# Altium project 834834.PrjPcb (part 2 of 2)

## Sheet 834834_ESCON2_EB_Nano_Nano-CAN-RS422.SchDoc
size A3; SheetNumber: 4; SheetTotal: 4; Created: MMAGHIN; Modified: MMAGADHA; Reviewed: MMAGMHA; CreatedDate: 10.07.2023; ReviewedDate: 03.10.2023; ModifiedDate1: 28.09.2023
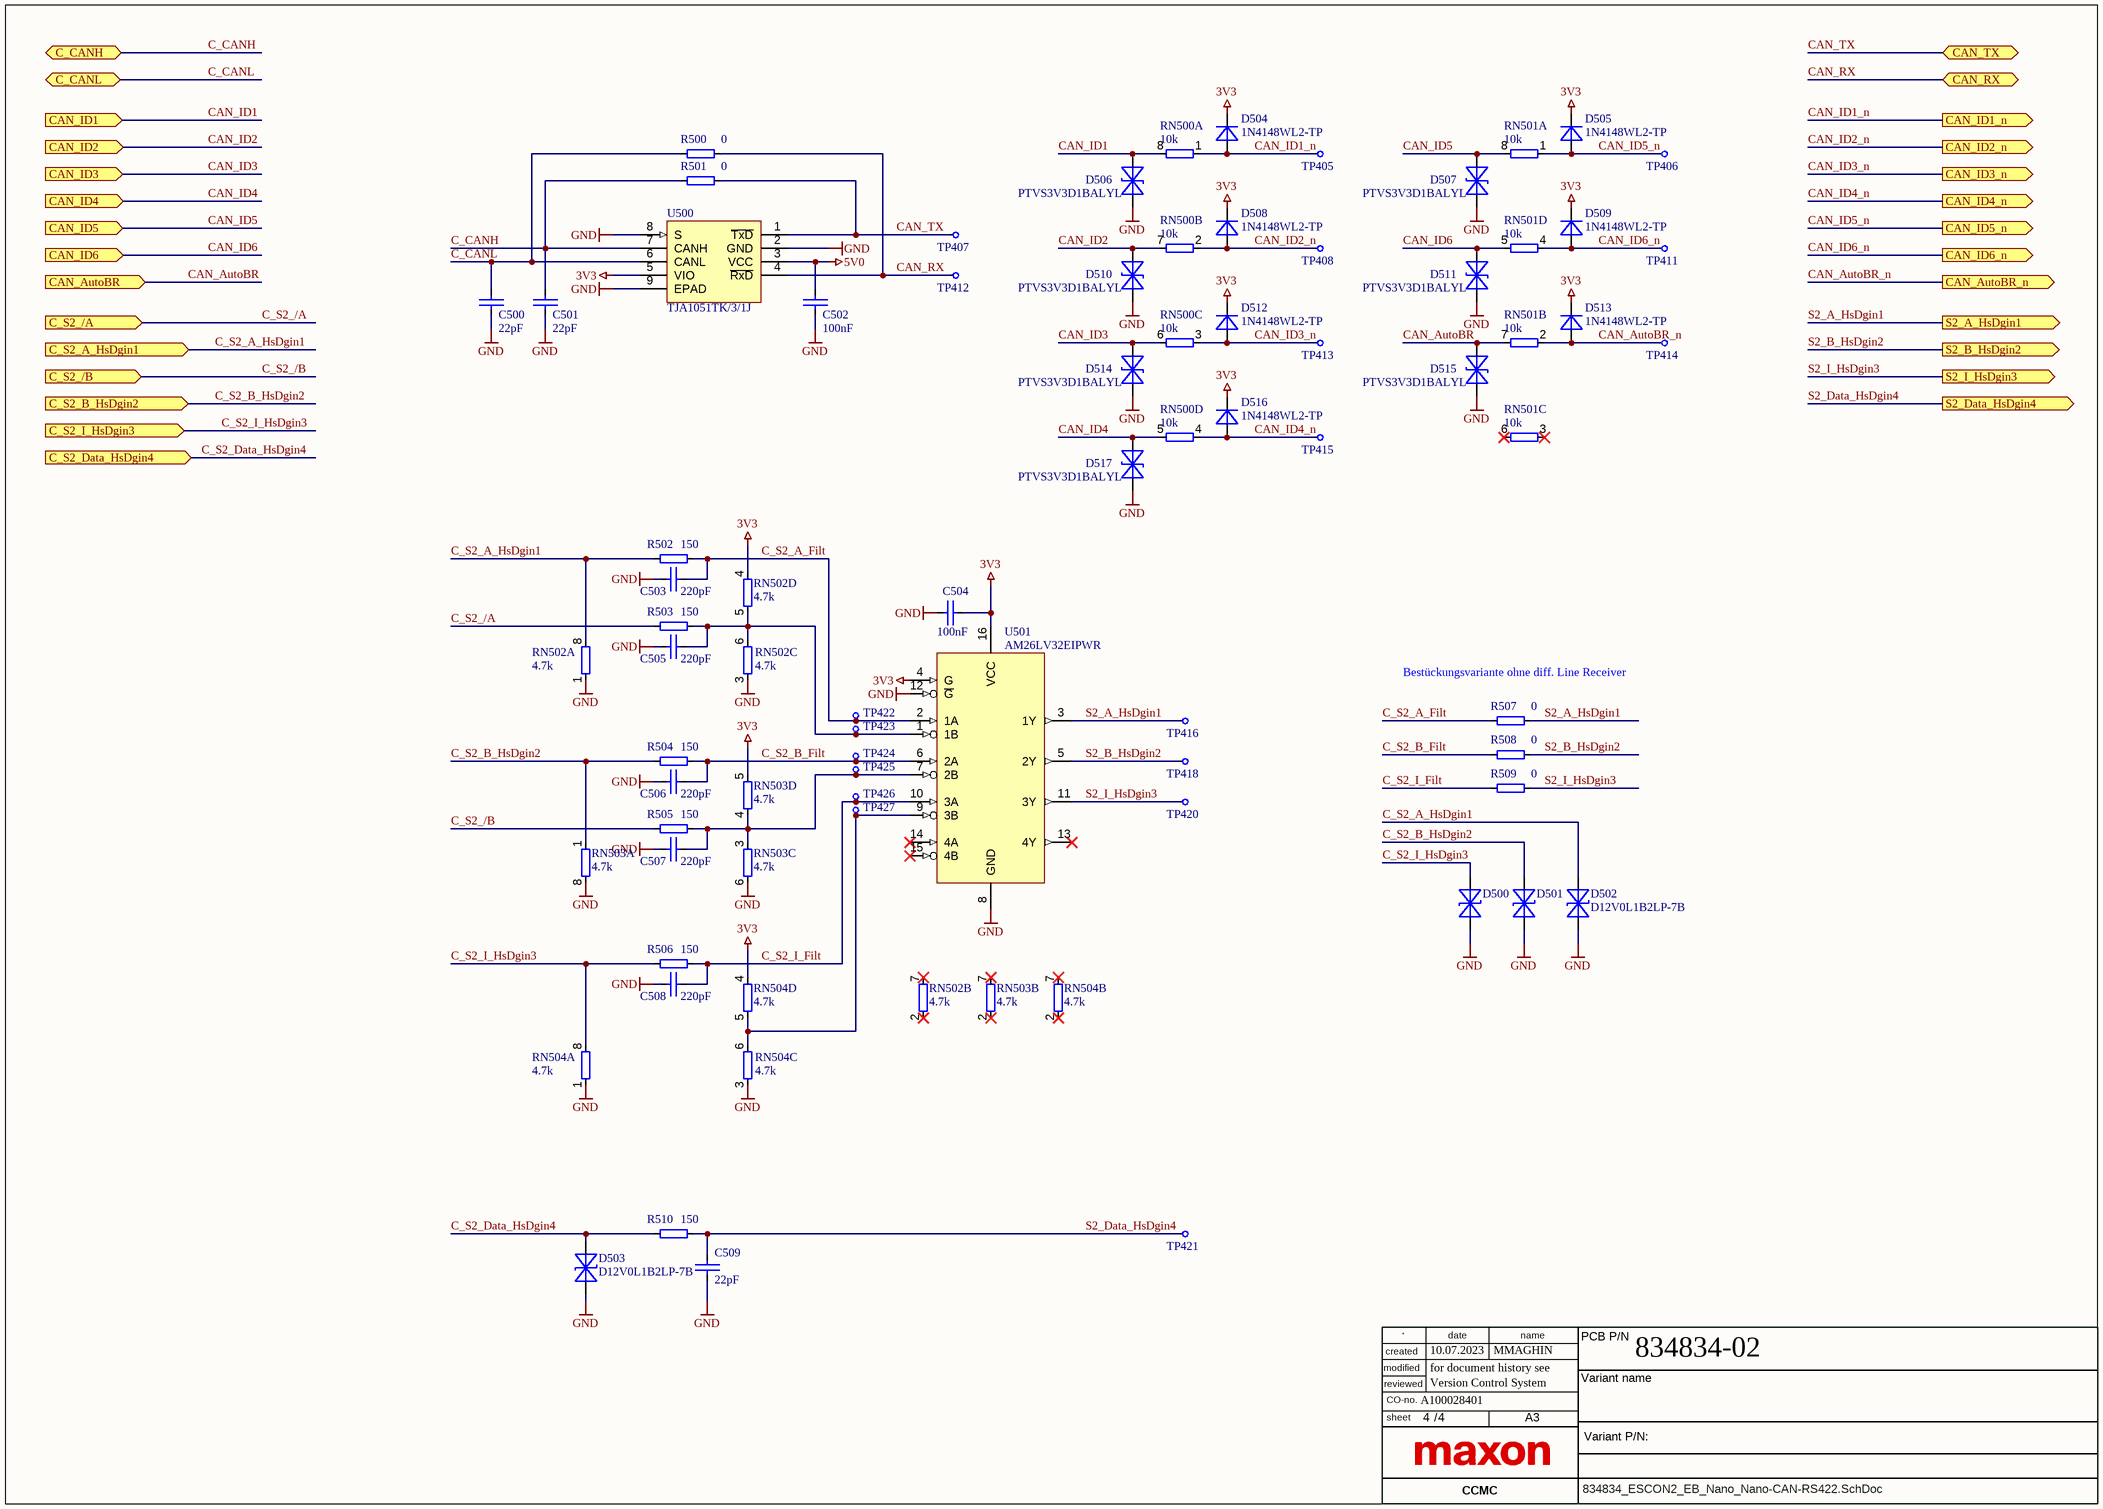
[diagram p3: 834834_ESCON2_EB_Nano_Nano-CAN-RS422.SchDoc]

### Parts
C500  value 22pF  [CAPC100X50X70L25N]  (hidden comment: 0402 22pF)
C501  value 22pF  [CAPC100X50X70L25N]  (hidden comment: 0402 22pF)
C502  value 100nF  [CAPC100X50X70L25N]  (hidden comment: 0402 100nF)
C503  value 220pF  [CAPC100X50X70L25N]  (hidden comment: 0402 220pF)
C504  value 100nF  [CAPC100X50X70L25N]  (hidden comment: 0402 100nF)
C505  value 220pF  [CAPC100X50X70L25N]  (hidden comment: 0402 220pF)
C506  value 220pF  [CAPC100X50X70L25N]  (hidden comment: 0402 220pF)
C507  value 220pF  [CAPC100X50X70L25N]  (hidden comment: 0402 220pF)
C508  value 220pF  [CAPC100X50X70L25N]  (hidden comment: 0402 220pF)
C509  value 22pF  [CAPC100X50X70L25N]  (hidden comment: 0402 22pF)
D500  D12V0L1B2LP-7B  [DIONPDFN2_102X60X60L25X50N]  (value not drawn)
D501  D12V0L1B2LP-7B  [DIONPDFN2_102X60X60L25X50N]  (value not drawn)
D502  D12V0L1B2LP-7B  [DIONPDFN2_102X60X60L25X50N]
D503  D12V0L1B2LP-7B  [DIONPDFN2_102X60X60L25X50N]
D504  1N4148WL2-TP  [DIODFN2_102X60X60L25X50N]
D505  1N4148WL2-TP  [DIODFN2_102X60X60L25X50N]
D506  PTVS3V3D1BALYL  [DIONPDFN2_102X60X60L25X50N]
D507  PTVS3V3D1BALYL  [DIONPDFN2_102X60X60L25X50N]
D508  1N4148WL2-TP  [DIODFN2_102X60X60L25X50N]
D509  1N4148WL2-TP  [DIODFN2_102X60X60L25X50N]
D510  PTVS3V3D1BALYL  [DIONPDFN2_102X60X60L25X50N]
D511  PTVS3V3D1BALYL  [DIONPDFN2_102X60X60L25X50N]
D512  1N4148WL2-TP  [DIODFN2_102X60X60L25X50N]
D513  1N4148WL2-TP  [DIODFN2_102X60X60L25X50N]
D514  PTVS3V3D1BALYL  [DIONPDFN2_102X60X60L25X50N]
D515  PTVS3V3D1BALYL  [DIONPDFN2_102X60X60L25X50N]
D516  1N4148WL2-TP  [DIODFN2_102X60X60L25X50N]
D517  PTVS3V3D1BALYL  [DIONPDFN2_102X60X60L25X50N]
R500  value 0  [RESC100X52X40L22N]  (hidden comment: 0402 0)
R501  value 0  [RESC100X52X40L22N]  (hidden comment: 0402 0)
R502  value 150  [RESC100X52X40L22N]  (hidden comment: 0402 150R)
R503  value 150  [RESC100X52X40L22N]  (hidden comment: 0402 150R)
R504  value 150  [RESC100X52X40L22N]  (hidden comment: 0402 150R)
R505  value 150  [RESC100X52X40L22N]  (hidden comment: 0402 150R)
R506  value 150  [RESC100X52X40L22N]  (hidden comment: 0402 150R)
R507  value 0  [RESC100X52X40L22N]  (hidden comment: 0402 0)
R508  value 0  [RESC100X52X40L22N]  (hidden comment: 0402 0)
R509  value 0  [RESC100X52X40L22N]  (hidden comment: 0402 0)
R510  value 150  [RESC100X52X40L22N]  (hidden comment: 0402 150R)
RN500  value 10k  [RESCAXS8P50_200X102X55L30X30N]  (hidden comment: 4x0402 10k)  (parts A,B,C,D of 4)
RN501  value 10k  [RESCAXS8P50_200X102X55L30X30N]  (hidden comment: 4x0402 10k)  (parts A,B,C,D of 4)
RN502  value 4.7k  [RESCAXS8P50_200X102X55L30X30N]  (hidden comment: 4x0402 4.7k)  (parts A,B,C,D of 4)
RN503  value 4.7k  [RESCAXS8P50_200X102X55L30X30N]  (hidden comment: 4x0402 4.7k)  (parts A,B,C,D of 4)
RN504  value 4.7k  [RESCAXS8P50_200X102X55L30X30N]  (hidden comment: 4x0402 4.7k)  (parts A,B,C,D of 4)
TP405  TPc120  [TESTPOINT_c120]  (value not drawn)  (no BOM)
TP406  TPc120  [TESTPOINT_c120]  (value not drawn)  (no BOM)
TP407  TPc120  [TESTPOINT_c120]  (value not drawn)  (no BOM)
TP408  TPc120  [TESTPOINT_c120]  (value not drawn)  (no BOM)
TP411  TPc120  [TESTPOINT_c120]  (value not drawn)  (no BOM)
TP412  TPc120  [TESTPOINT_c120]  (value not drawn)  (no BOM)
TP413  TPc120  [TESTPOINT_c120]  (value not drawn)  (no BOM)
TP414  TPc120  [TESTPOINT_c120]  (value not drawn)  (no BOM)
TP415  TPc120  [TESTPOINT_c120]  (value not drawn)  (no BOM)
TP416  TPc120  [TESTPOINT_c120]  (value not drawn)  (no BOM)
TP418  TPc120  [TESTPOINT_c120]  (value not drawn)  (no BOM)
TP420  TPc120  [TESTPOINT_c120]  (value not drawn)  (no BOM)
TP421  TPc120  [TESTPOINT_c120]  (value not drawn)  (no BOM)
TP422  TPc120  [TESTPOINT_c120]  (value not drawn)  (no BOM)
TP423  TPc120  [TESTPOINT_c120]  (value not drawn)  (no BOM)
TP424  TPc120  [TESTPOINT_c120]  (value not drawn)  (no BOM)
TP425  TPc120  [TESTPOINT_c120]  (value not drawn)  (no BOM)
TP426  TPc120  [TESTPOINT_c120]  (value not drawn)  (no BOM)
TP427  TPc120  [TESTPOINT_c120]  (value not drawn)  (no BOM)
U500  TJA1051TK/3/1J  [SON9P65_300X300X100L40X30T240X160N]
U501  AM26LV32EIPWR  [SOP16P65_500X640X120L83X24N]

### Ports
C_CANH (bidir), C_CANL (bidir), C_S2_/A (in), C_S2_/B (in), C_S2_A_HsDgin1 (in), C_S2_B_HsDgin2 (in), C_S2_Data_HsDgin4 (in), C_S2_I_HsDgin3 (in), CAN_AutoBR (in), CAN_AutoBR_n (out), CAN_ID1 (in), CAN_ID1_n (out), CAN_ID2 (in), CAN_ID2_n (out), CAN_ID3 (in), CAN_ID3_n (out), CAN_ID4 (in), CAN_ID4_n (out), CAN_ID5 (in), CAN_ID5_n (out), CAN_ID6 (in), CAN_ID6_n (out), CAN_RX (bidir), CAN_TX (bidir), S2_A_HsDgin1 (out), S2_B_HsDgin2 (out), S2_Data_HsDgin4 (out), S2_I_HsDgin3 (out)

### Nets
3V3: C504.1 D504.1(C) D505.1(C) D508.1(C) D509.1(C) D512.1(C) D513.1(C) D516.1(C) RN502.4 RN503.5 RN504.4 U500.5(VIO) U501.4(G) U501.16(VCC)
5V0: C502.2 U500.3(VCC)
GND: C500.2 C501.2 C502.1 C503.2 C504.2 C505.2 C506.2 C507.2 C508.2 C509.2 D500.1 D501.1 D502.1 D503.1 D506.2 D507.2 D510.2 D511.2 D514.2 D515.2 D517.2 RN502.1 RN502.3 RN503.6 RN503.8 RN504.1 RN504.3 U500.2(GND) U500.8(S) U500.9(EPAD) U501.8(GND) U501.12(~{G})
C_CANH: C501.1 R501.2 U500.7(CANH) ; port C_CANH
C_CANL: C500.1 R500.2 U500.6(CANL) ; port C_CANL
C_S2_/A: R503.1 ; port C_S2_/A
C_S2_/B: R505.1 ; port C_S2_/B
C_S2_A_Filt: C503.1 R502.2 R507.2 TP422.1 U501.2(1A)
C_S2_A_HsDgin1: D502.2 R502.1 RN502.8 ; port C_S2_A_HsDgin1
C_S2_B_Filt: C506.1 R504.2 R508.2 TP424.1 U501.6(2A)
C_S2_B_HsDgin2: D501.2 R504.1 RN503.1 ; port C_S2_B_HsDgin2
C_S2_Data_HsDgin4: D503.2 R510.1 ; port C_S2_Data_HsDgin4
C_S2_I_Filt: C508.1 R506.2 R509.2 TP426.1 U501.10(3A)
C_S2_I_HsDgin3: D500.2 R506.1 RN504.8 ; port C_S2_I_HsDgin3
CAN_AutoBR: D515.1 RN501.7 ; port CAN_AutoBR
CAN_AutoBR_n: D513.2(A) RN501.2 TP414.1 ; port CAN_AutoBR_n
CAN_ID1: D506.1 RN500.8 ; port CAN_ID1
CAN_ID1_n: D504.2(A) RN500.1 TP405.1 ; port CAN_ID1_n
CAN_ID2: D510.1 RN500.7 ; port CAN_ID2
CAN_ID2_n: D508.2(A) RN500.2 TP408.1 ; port CAN_ID2_n
CAN_ID3: D514.1 RN500.6 ; port CAN_ID3
CAN_ID3_n: D512.2(A) RN500.3 TP413.1 ; port CAN_ID3_n
CAN_ID4: D517.1 RN500.5 ; port CAN_ID4
CAN_ID4_n: D516.2(A) RN500.4 TP415.1 ; port CAN_ID4_n
CAN_ID5: D507.1 RN501.8 ; port CAN_ID5
CAN_ID5_n: D505.2(A) RN501.1 TP406.1 ; port CAN_ID5_n
CAN_ID6: D511.1 RN501.5 ; port CAN_ID6
CAN_ID6_n: D509.2(A) RN501.4 TP411.1 ; port CAN_ID6_n
CAN_RX: R500.1 TP412.1 U500.4(~{RxD}) ; port CAN_RX
CAN_TX: R501.1 TP407.1 U500.1(~{TxD}) ; port CAN_TX
S2_A_HsDgin1: R507.1 TP416.1 U501.3(1Y) ; port S2_A_HsDgin1
S2_B_HsDgin2: R508.1 TP418.1 U501.5(2Y) ; port S2_B_HsDgin2
S2_Data_HsDgin4: C509.1 R510.2 TP421.1 ; port S2_Data_HsDgin4
S2_I_HsDgin3: R509.1 TP420.1 U501.11(3Y) ; port S2_I_HsDgin3
NetC505_1: C505.1 R503.2 RN502.5 RN502.6 TP423.1 U501.1(1B)
NetC507_1: C507.1 R505.2 RN503.3 RN503.4 TP425.1 U501.7(2B)
NetRN504_5: RN504.5 RN504.6 TP427.1 U501.9(3B)

Not connected (* = marked no-connect by the designer): RN501 3* 6*; RN502 2* 7*; RN503 2* 7*; RN504 2* 7*; U501 13(4Y)* 14(4A)* 15(4B)*

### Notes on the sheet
- (near R507) Bestückungsvariante ohne diff. Line Receiver

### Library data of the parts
C500 C501 C509 = CMP-000706-3: 22pF C0G/NP0 >=50V 10%; Part Number: Ceramic, 0402, 22pF, 10%, >=50V, C0G/NP0, @, Soft Termination: N, -55°C to 125°C; Manufacturer: X; Case (Metric): 1005; Soft Termination: N; Maximum Working Voltage: 50V
C502 C504 = CMP-000709-3: 100nF X7R >=16V 20%; Part Number: Ceramic, 0402, 100nF, 20%, >=16V, X7R, @, Soft Termination: N, -55°C to 125°C; Manufacturer: X; Maximum Working Voltage: 16V; Soft Termination: N; Case (Metric): 1005
C503 C505-C508 = CMP-000726-3: 220pF C0G/NP0/X7R >=50V 10%; Manufacturer: X; Part Number: Ceramic, 0402, 220pF, 10%, >=50V, C0G/NP0/X7R, @, Soft Termination: N, -55°C to 125°C; Maximum Working Voltage: 50V; Case (Metric): 1005; Soft Termination: N
D500-D503 = CMP-001106-5: Transient Voltage Suppressor Diode, 12V V(RWM), Bidirectional, 100W, 1 Element, SOD-882/DFN1006; Manufacturer: Diodes; Element Configuration: Single; Breakdown Voltage: 13V; Polarity: Bipolar
D504 D505 D508 D509 D512 D513 D516 = CMP-000606-13: Diode Switching, >=70V, >=150mA, SOD882/DFN1006/0402/SOD-923F; Manufacturer: MCC; Polarity: Unipolar; Recovery time: 4ns; Reverse Voltage: 70V; Element Configuration: Single; RMS Current: 150mA
D506 D507 D510 D511 D514 D515 D517 = CMP-001117-7: Transient Voltage Suppressor Diode, 3.3V V(RWM), Bidirectional, 30W, 1 Element, SOD-882/DFN1006; Manufacturer: Nexperia; Element Configuration: Single; Breakdown Voltage: 4V; Polarity: Bipolar
R500 R501 R507-R509 = CMP-000466-10: 0R Jumper; Part Number: Thick-Film, 0402, 0, -55°C to 155°C; Manufacturer: X; Case (Metric): 1050; RMS Current: 1A; Maximum Overload Voltage: 100V; Max Junction Temperature: 155°C; Maximum Working Voltage: 50V
R502-R506 R510 = CMP-000169-11: 150R 1% 62.5mW 100ppm; Part Number: Thick-Film, 0402, 150, 1%, 62.5mW@70°C, 50V, 100ppm, -55°C to 155°C; Manufacturer: X; Max Junction Temperature: 155°C; AECQ: N; Case (Metric): 1050; Power Rating Temperature: 70°C; Maximum Working Voltage: 50V; Maximum Overload Voltage: 100V
RN500 RN501 = CMP-000792-5: 4x10k 5% 62.5mW 200ppm; Part Number: Thick-Film Concave/Convex, 4x0402, 10k, 5%, 62.5mW@70°C, 25V, 200ppm, -55°C to 125°C; Manufacturer: X; Max Junction Temperature: 125°C; AECQ: N; Case (Metric): 2010; Power Rating Temperature: 70°C; Maximum Working Voltage: 25V; Maximum Overload Voltage: 50V
RN502-RN504 = CMP-000784-5: 4x4.7k 5% 62.5mW 200ppm; Part Number: Thick-Film Concave/Convex, 4x0402, 4.7k, 5%, 62.5mW@70°C, 25V, 200ppm, -55°C to 125°C; Manufacturer: X; Max Junction Temperature: 125°C; AECQ: N; Case (Metric): 2010; Power Rating Temperature: 70°C; Maximum Working Voltage: 25V; Maximum Overload Voltage: 50V
TP405-TP408 TP411-TP416 TP418 TP420-TP427 = CMP-000014-7: Test Point; 1 pin, 1.20 mm D
U500 = CMP-000672-8: High Speed CAN Transceiver, Single, 5V, HVSON-8; Manufacturer: NXP Semiconductors; Min Supply Voltage: 4.5V; Max Supply Voltage: 5.5V
U501 = CMP-001174-5: Low-Voltage High-Speed Quadruple Differential Line Receiver With +/-15-kV IEC ESD 16-TSSOP -40 to 85°C; Manufacturer: Texas Instruments; Max Supply Voltage: 3.6V; Min Supply Voltage: 3V

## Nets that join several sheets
3V3: 834834_ESCON2_EB_Nano_Common-Components (C200.2 TP202.1 U200.5 X200.1), 834834_ESCON2_EB_Nano_Nano-Components (6 pins), 834834_ESCON2_EB_Nano_Nano-CAN-RS422 (14 pins)
5V0: 834834_ESCON2_EB_Nano_Common-Components (8 pins), 834834_ESCON2_EB_Nano_Nano-Components (10 pins), 834834_ESCON2_EB_Nano_Nano-CAN-RS422 (C502.2 U500.3)
5V0_sensor1_2: 834834_ESCON2_EB_Nano_Common-Components (D201.2 X4.5 X5.2), 834834_ESCON2_EB_Nano_Nano-Components (R421.1 R429.2 TP404.1)
C_VP: 834834_ESCON2_EB_Nano_Common-Components (TP201.1 X1.2), 834834_ESCON2_EB_Nano_Nano-Components (F400.1)
GND: 834834_ESCON2_EB_Nano_Common-Components (65 pins), 834834_ESCON2_EB_Nano_Nano-Components (57 pins), 834834_ESCON2_EB_Nano_Nano-CAN-RS422 (32 pins)
C_AnIN1+: 834834_ESCON2_EB_Nano_Common-Components (TP230.1 X8.1), 834834_ESCON2_EB_Nano_Nano-Components (D404.1 X400a.26 X400b.26)
C_AnIN2+: 834834_ESCON2_EB_Nano_Common-Components (TP232.1 X8.3), 834834_ESCON2_EB_Nano_Nano-Components (D403.1 X400a.28 X400b.28)
C_AnOUT1: 834834_ESCON2_EB_Nano_Common-Components (TP234.1 X8.5), 834834_ESCON2_EB_Nano_Nano-Components (D406.2 X400a.30 X400b.30)
C_AnOUT2: 834834_ESCON2_EB_Nano_Common-Components (TP237.1 X8.6), 834834_ESCON2_EB_Nano_Nano-Components (D405.2 X400a.32 X400b.32)
C_CANH: 834834_ESCON2_EB_Nano_Common-Components (SW1.7 TP240.1 X11.1 X12.1), 834834_ESCON2_EB_Nano_Nano-CAN-RS422 (C501.1 R501.2 U500.7)
C_CANL: 834834_ESCON2_EB_Nano_Common-Components (R209.2 TP241.1 X11.2 X12.2), 834834_ESCON2_EB_Nano_Nano-CAN-RS422 (C500.1 R500.2 U500.6)
C_DigIN1: 834834_ESCON2_EB_Nano_Common-Components (D203.2 TP204.1 X7.1), 834834_ESCON2_EB_Nano_Nano-Components (RN400.5 RN400.6)
C_DigIN2: 834834_ESCON2_EB_Nano_Common-Components (D202.2 TP205.1 X7.2), 834834_ESCON2_EB_Nano_Nano-Components (RN400.7 RN400.8)
C_DigIN3: 834834_ESCON2_EB_Nano_Common-Components (D210.2 TP269.1 X7.3), 834834_ESCON2_EB_Nano_Nano-Components (X400a.27 X400b.27)
C_DigIN4: 834834_ESCON2_EB_Nano_Common-Components (D209.2 TP270.1 X7.4), 834834_ESCON2_EB_Nano_Nano-Components (X400a.29 X400b.29)
C_MotorTemp: 834834_ESCON2_EB_Nano_Common-Components (TP260.1 X16.2), 834834_ESCON2_EB_Nano_Nano-Components (C421.2 Q400.2 R427.2)
C_S1_Hall1: 834834_ESCON2_EB_Nano_Common-Components (TP266.1 X4.1), 834834_ESCON2_EB_Nano_Nano-Components (X400a.13 X400b.13)
C_S1_Hall2: 834834_ESCON2_EB_Nano_Common-Components (TP267.1 X4.2), 834834_ESCON2_EB_Nano_Nano-Components (X400a.15 X400b.15)
C_S1_Hall3: 834834_ESCON2_EB_Nano_Common-Components (TP268.1 X4.3), 834834_ESCON2_EB_Nano_Nano-Components (X400a.17 X400b.17)
C_S2_/A: 834834_ESCON2_EB_Nano_Common-Components (TP216.1 X5.5), 834834_ESCON2_EB_Nano_Nano-CAN-RS422 (R503.1)
C_S2_/B: 834834_ESCON2_EB_Nano_Common-Components (TP218.1 X5.7), 834834_ESCON2_EB_Nano_Nano-CAN-RS422 (R505.1)
C_S2_A_HsDgin1: 834834_ESCON2_EB_Nano_Common-Components (TP217.1 X5.6), 834834_ESCON2_EB_Nano_Nano-CAN-RS422 (D502.2 R502.1 RN502.8)
C_S2_B_HsDgin2: 834834_ESCON2_EB_Nano_Common-Components (TP219.1 X5.8), 834834_ESCON2_EB_Nano_Nano-CAN-RS422 (D501.2 R504.1 RN503.1)
C_S2_Data_HsDgin4: 834834_ESCON2_EB_Nano_Common-Components (TP213.1 X5.1), 834834_ESCON2_EB_Nano_Nano-CAN-RS422 (D503.2 R510.1)
C_S2_I_HsDgin3: 834834_ESCON2_EB_Nano_Common-Components (TP220.1 X5.10), 834834_ESCON2_EB_Nano_Nano-CAN-RS422 (D500.2 R506.1 RN504.8)
C_USB_D+: 834834_ESCON2_EB_Nano_Common-Components (D208.5 TP251.1 X13.AB6), 834834_ESCON2_EB_Nano_Nano-Components (X400a.46 X400b.46)
C_USB_D-: 834834_ESCON2_EB_Nano_Common-Components (D208.1 TP252.1 X13.AB7), 834834_ESCON2_EB_Nano_Nano-Components (X400a.48 X400b.48)
C_USB_VBUS: 834834_ESCON2_EB_Nano_Common-Components (C206.2 TP247.1 X13.AB49), 834834_ESCON2_EB_Nano_Nano-Components (X400a.44 X400b.44)
C_W1: 834834_ESCON2_EB_Nano_Common-Components (TP207.1 X3.1), 834834_ESCON2_EB_Nano_Nano-Components (C402.2 C405.2 L400.2)
C_W2: 834834_ESCON2_EB_Nano_Common-Components (TP208.1 X3.2), 834834_ESCON2_EB_Nano_Nano-Components (C403.2 C406.2 L401.2)
C_W3: 834834_ESCON2_EB_Nano_Common-Components (TP209.1 X3.3), 834834_ESCON2_EB_Nano_Nano-Components (C404.2 C407.2 L402.2)
CAN_AutoBR: 834834_ESCON2_EB_Nano_Common-Components (SW1.11 TP253.1), 834834_ESCON2_EB_Nano_Nano-CAN-RS422 (D515.1 RN501.7)
CAN_AutoBR_n: 834834_ESCON2_EB_Nano_Nano-Components (X400a.35 X400b.35), 834834_ESCON2_EB_Nano_Nano-CAN-RS422 (D513.2 RN501.2 TP414.1)
CAN_ID1: 834834_ESCON2_EB_Nano_Common-Components (SW1.16 TP239.1), 834834_ESCON2_EB_Nano_Nano-CAN-RS422 (D506.1 RN500.8)
CAN_ID1_n: 834834_ESCON2_EB_Nano_Nano-Components (X400a.37 X400b.37), 834834_ESCON2_EB_Nano_Nano-CAN-RS422 (D504.2 RN500.1 TP405.1)
CAN_ID2: 834834_ESCON2_EB_Nano_Common-Components (SW1.15 TP243.1), 834834_ESCON2_EB_Nano_Nano-CAN-RS422 (D510.1 RN500.7)
CAN_ID2_n: 834834_ESCON2_EB_Nano_Nano-Components (X400a.39 X400b.39), 834834_ESCON2_EB_Nano_Nano-CAN-RS422 (D508.2 RN500.2 TP408.1)
CAN_ID3: 834834_ESCON2_EB_Nano_Common-Components (SW1.14 TP245.1), 834834_ESCON2_EB_Nano_Nano-CAN-RS422 (D514.1 RN500.6)
CAN_ID3_n: 834834_ESCON2_EB_Nano_Nano-Components (X400a.41 X400b.41), 834834_ESCON2_EB_Nano_Nano-CAN-RS422 (D512.2 RN500.3 TP413.1)
CAN_ID4: 834834_ESCON2_EB_Nano_Common-Components (SW1.13 TP248.1), 834834_ESCON2_EB_Nano_Nano-CAN-RS422 (D517.1 RN500.5)
CAN_ID4_n: 834834_ESCON2_EB_Nano_Nano-Components (X400a.43 X400b.43), 834834_ESCON2_EB_Nano_Nano-CAN-RS422 (D516.2 RN500.4 TP415.1)
CAN_ID5: 834834_ESCON2_EB_Nano_Common-Components (SW1.12 TP250.1), 834834_ESCON2_EB_Nano_Nano-CAN-RS422 (D507.1 RN501.8)
CAN_ID5_n: 834834_ESCON2_EB_Nano_Nano-Components (X400a.45 X400b.45), 834834_ESCON2_EB_Nano_Nano-CAN-RS422 (D505.2 RN501.1 TP406.1)
CAN_ID6: 834834_ESCON2_EB_Nano_Common-Components (SW1.9 TP257.1), 834834_ESCON2_EB_Nano_Nano-CAN-RS422 (D511.1 RN501.5)
CAN_ID6_n: 834834_ESCON2_EB_Nano_Nano-Components (X400a.47 X400b.47), 834834_ESCON2_EB_Nano_Nano-CAN-RS422 (D509.2 RN501.4 TP411.1)
CAN_RX: 834834_ESCON2_EB_Nano_Nano-Components (X400a.53 X400b.53), 834834_ESCON2_EB_Nano_Nano-CAN-RS422 (R500.1 TP412.1 U500.4)
CAN_TX: 834834_ESCON2_EB_Nano_Nano-Components (X400a.51 X400b.51), 834834_ESCON2_EB_Nano_Nano-CAN-RS422 (R501.1 TP407.1 U500.1)
DBG_SWCLK: 834834_ESCON2_EB_Nano_Common-Components (TP222.1 X200.4), 834834_ESCON2_EB_Nano_Nano-Components (X400a.34 X400b.34)
DBG_SWDIO: 834834_ESCON2_EB_Nano_Common-Components (TP221.1 X200.2), 834834_ESCON2_EB_Nano_Nano-Components (X400a.36 X400b.36)
DigOUT1: 834834_ESCON2_EB_Nano_Common-Components (R214.2 TP235.1 U201.1 U201.2), 834834_ESCON2_EB_Nano_Nano-Components (X400a.31 X400b.31)
DigOUT2: 834834_ESCON2_EB_Nano_Common-Components (R215.2 TP236.1 U202.1 U202.2), 834834_ESCON2_EB_Nano_Nano-Components (X400a.33 X400b.33)
LED_Axis_gn: 834834_ESCON2_EB_Nano_Common-Components (R212.1 TP261.1), 834834_ESCON2_EB_Nano_Nano-Components (X400a.21 X400b.21)
LED_Axis_rd: 834834_ESCON2_EB_Nano_Common-Components (R211.1 TP258.1), 834834_ESCON2_EB_Nano_Nano-Components (X400a.19 X400b.19)
S2_A_HsDgin1: 834834_ESCON2_EB_Nano_Nano-Components (X400a.14 X400b.14), 834834_ESCON2_EB_Nano_Nano-CAN-RS422 (R507.1 TP416.1 U501.3)
S2_B_HsDgin2: 834834_ESCON2_EB_Nano_Nano-Components (X400a.16 X400b.16), 834834_ESCON2_EB_Nano_Nano-CAN-RS422 (R508.1 TP418.1 U501.5)
S2_Clock: 834834_ESCON2_EB_Nano_Common-Components (R213.2 TP206.1 U200.2), 834834_ESCON2_EB_Nano_Nano-Components (X400a.22 X400b.22)
S2_Data_HsDgin4: 834834_ESCON2_EB_Nano_Nano-Components (X400a.20 X400b.20), 834834_ESCON2_EB_Nano_Nano-CAN-RS422 (C509.1 R510.2 TP421.1)
S2_I_HsDgin3: 834834_ESCON2_EB_Nano_Nano-Components (X400a.18 X400b.18), 834834_ESCON2_EB_Nano_Nano-CAN-RS422 (R509.1 TP420.1 U501.11)
SYS_/Reset: 834834_ESCON2_EB_Nano_Common-Components (C203.2 TP228.1 X200.10), 834834_ESCON2_EB_Nano_Nano-Components (X400a.38 X400b.38)
UART_RxD: 834834_ESCON2_EB_Nano_Common-Components (C212.2 TP212.1 U203.12), 834834_ESCON2_EB_Nano_Nano-Components (X400a.54 X400b.54)
UART_TxD: 834834_ESCON2_EB_Nano_Common-Components (TP211.1 U203.11), 834834_ESCON2_EB_Nano_Nano-Components (R418.1)

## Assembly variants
834835: not fitted C212 C401 C408 C409 C410 C411 C412 C413 D202 D203 D209 D210 D500 D501 D502 R210 R421 R500 R501 R507 R508 R509 X200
